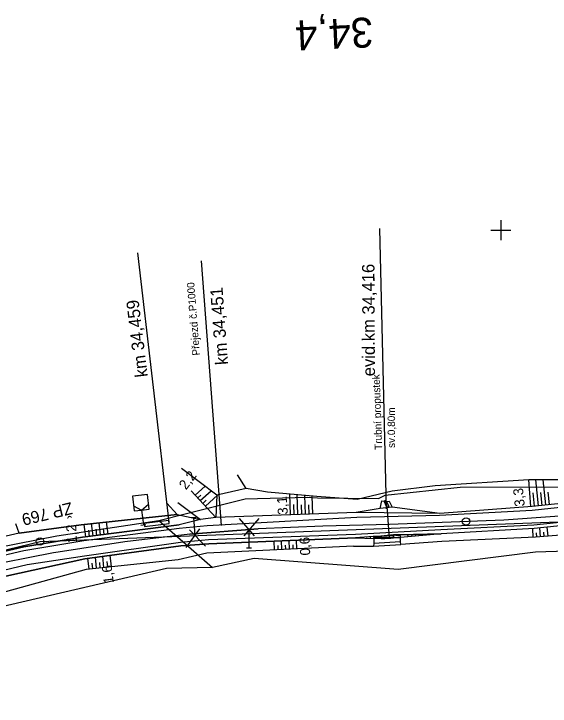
# Model space of a CAD drawing. Extents: x -805730 to -804640, y -1150889 to -1150366.
# Drawn here: x -805297.6 to -805190.1, y -1150695.5 to -1150556.6 of the extents above; entities that cross this region are included whole.
import ezdxf

# ---------------------------------------------------------------- set-up
doc = ezdxf.new("R2010")
doc.units = 0
for name, color, linetype in [('0381KM032-037P - Vrstva 1', 7, 'Continuous'), ('0381KM032-037P - Vrstva 17', 7, 'Continuous'), ('0381KM032-037P - Vrstva 19', 7, 'Continuous'), ('0381KM032-037P - Vrstva 4', 7, 'Continuous'), ('0381KM032-037P - Vrstva 48', 7, 'Continuous'), ('0381KM032-037P - Vrstva 49', 7, 'Continuous'), ('0381KM032-037P - Vrstva 51', 7, 'Continuous'), ('0381KM032-037P - Vrstva 55', 7, 'Continuous'), ('0381KM032-037P - Vrstva 7', 7, 'Continuous'), ('0381KM032-037P - Vrstva 9', 7, 'Continuous'), ('hran DP - hran DP', 7, 'Continuous'), ('krizky_1000 - Vrstva 1', 7, 'Continuous'), ('vyt_sit - ohrožené', 7, 'Continuous'), ('vyt_sit - polygon', 7, 'Continuous')]:
    doc.layers.add(name, color=color, linetype=linetype)

msp = doc.modelspace()

# ---------------------------------------------------------------- linework, layer by layer
at = {"layer": '0381KM032-037P - Vrstva 1'}
for points in [[(-805182.79, -1150656.72), (-805189.2, -1150657.4), (-805199.42, -1150658.12), (-805222.35, -1150659), (-805235.71, -1150659.34), (-805248.65, -1150659.92), (-805262.34, -1150660.99)], [(-805262.34, -1150660.99), (-805275.34, -1150662.5), (-805288.75, -1150664.54), (-805289.64, -1150664.68), (-805304.6, -1150667.62), (-805306.42, -1150668.06)]]:
    msp.add_lwpolyline(points, dxfattribs=at)
at = {"layer": '0381KM032-037P - Vrstva 17'}
for points in [[(-805070.8, -1150598.9), (-805121.06, -1150638.84), (-805152.76, -1150646.7), (-805170.92, -1150650.08), (-805194.39, -1150650.05), (-805213.2, -1150651.26), (-805221.79, -1150652.33), (-805228.79, -1150654.03)], [(-805228.79, -1150654.03), (-805236.91, -1150653.41), (-805246.77, -1150652.51), (-805251.08, -1150651.83), (-805252.77, -1150649.08)], [(-805266.94, -1150654.72), (-805264.88, -1150657), (-805284.09, -1150659.06), (-805296.52, -1150660.78), (-805297.22, -1150658.9)]]:
    msp.add_lwpolyline(points, dxfattribs=at)
at = {"layer": '0381KM032-037P - Vrstva 19'}
for p, q in [((-805224.33, -1150599.68), (-805223.01, -1150655.91)), ((-805222.9, -1150655.44), (-805223.36, -1150654.35)), ((-805222.89, -1150654.41), (-805222.49, -1150655.3)), ((-805225.47, -1150661.83), (-805224.04, -1150661.74)), ((-805224.04, -1150661.49), (-805224.04, -1150661.74)), ((-805221.51, -1150661.6), (-805224, -1150661.7)), ((-805224, -1150661.7), (-805224, -1150661.8)), ((-805224, -1150661.8), (-805221.51, -1150661.7)), ((-805223.99, -1150661.38), (-805221.54, -1150661.24)), ((-805221.51, -1150661.18), (-805221.49, -1150661.72)), ((-805221.51, -1150661.7), (-805221.51, -1150661.6))]:
    msp.add_line(p, q, dxfattribs=at)
msp.add_lwpolyline([(-805224.22, -1150655.82), (-805223.87, -1150654.3), (-805223.36, -1150654.35), (-805223.23, -1150654.21), (-805222.89, -1150654.41), (-805222.41, -1150654.36), (-805221.82, -1150655.55)], close=True, dxfattribs=at)
for points in [[(-805223.23, -1150654.21), (-805222.87, -1150655.41), (-805222.4, -1150661.78)], [(-805225.57, -1150661.42), (-805224.05, -1150661.35), (-805223.99, -1150661.38)], [(-805225.57, -1150661.42), (-805225.56, -1150661.53), (-805225.47, -1150661.83), (-805225.46, -1150662.84), (-805225.54, -1150663.4), (-805220.04, -1150663.05), (-805220.11, -1150662.52), (-805225.46, -1150662.84)], [(-805225.56, -1150661.53), (-805224.04, -1150661.49), (-805224.05, -1150661.35)], [(-805224, -1150661.7), (-805224.04, -1150661.74), (-805224.02, -1150661.84), (-805223.26, -1150661.81), (-805222.4, -1150661.78)], [(-805223.99, -1150661.81), (-805224, -1150661.8)], [(-805223.99, -1150661.38), (-805223.99, -1150661.81), (-805221.51, -1150661.69)], [(-805222.4, -1150661.78), (-805221.56, -1150661.7), (-805221.49, -1150661.72)], [(-805221.51, -1150661.7), (-805221.51, -1150661.69), (-805221.54, -1150661.24), (-805221.52, -1150661.12), (-805220.23, -1150661.07), (-805220.19, -1150661.33), (-805220.13, -1150661.62)], [(-805220.19, -1150661.33), (-805221.51, -1150661.18), (-805221.52, -1150661.12)], [(-805220.11, -1150662.52), (-805220.13, -1150661.62), (-805221.49, -1150661.72), (-805221.51, -1150661.6)]]:
    msp.add_lwpolyline(points, dxfattribs=at)
for centre, major_axis, ratio, start_param, end_param in [((-805222.69, -1150655.38), (0.215, 0.047), 0.800066, 3.235081, 6.495155), ((-805222.47, -1150661.77), (-0.4, -0.017), 0.197294, 3.17264, 6.315874), ((-805222.47, -1150661.77), (0.4, 0.019), 0.014453, 3.164337, 6.322931)]:
    msp.add_ellipse(centre, major_axis=major_axis, ratio=ratio, start_param=start_param, end_param=end_param, dxfattribs=at)
at = {"layer": '0381KM032-037P - Vrstva 4'}
for p, q in [((-805260.04, -1150606.16), (-805256.03, -1150659.22)), ((-805261.09, -1150657.61), (-805262.09, -1150657.68)), ((-805261.59, -1150657.65), (-805261.34, -1150661.14)), ((-805252.46, -1150657.82), (-805249.46, -1150661.32)), ((-805251.46, -1150661.32), (-805248.46, -1150657.82)), ((-805260.43, -1150659.92), (-805263.17, -1150663.62)), ((-805259.18, -1150663.34), (-805262.42, -1150660.06)), ((-805262.34, -1150660.99), (-805248.65, -1150659.92)), ((-805250.46, -1150663.67), (-805250.46, -1150660.17)), ((-805250.96, -1150663.67), (-805249.96, -1150663.67))]:
    msp.add_line(p, q, dxfattribs=at)
for points in [[(-805097.6, -1150634.39), (-805112.1, -1150639.75), (-805119.36, -1150642.27), (-805152.08, -1150650.89), (-805169.94, -1150653.7), (-805193.71, -1150656.24), (-805212.28, -1150657.22)], [(-805096.44, -1150637.01), (-805110.9, -1150642.46), (-805118.26, -1150644.98), (-805151.42, -1150653.61), (-805169.41, -1150656.67), (-805193.4, -1150659.17), (-805212.01, -1150660.08)], [(-805134.98, -1150644.55), (-805152.23, -1150649.93), (-805170.06, -1150652.94), (-805193.76, -1150655.4), (-805212.2, -1150656.84), (-805228.99, -1150656.61)], [(-805134.56, -1150650.98), (-805151.31, -1150654.12), (-805169.36, -1150657.36), (-805193.31, -1150659.84), (-805211.96, -1150660.88), (-805220.23, -1150661.07)], [(-805228.99, -1150656.61), (-805257.13, -1150657.62), (-805260.23, -1150658.03), (-805264.49, -1150659.11), (-805283.86, -1150661.58), (-805295.64, -1150663.5), (-805324.06, -1150670.09), (-805365.63, -1150680.4), (-805372.09, -1150681.89), (-805381.91, -1150683.24), (-805417.14, -1150687.42), (-805420, -1150686.97)], [(-805212.28, -1150657.22), (-805228.89, -1150657.63), (-805258.88, -1150659.27), (-805264.46, -1150659.8), (-805283.61, -1150662.28), (-805295.6, -1150664.3), (-805323.97, -1150670.91), (-805365.39, -1150681.52), (-805371.9, -1150683.14), (-805381.67, -1150685.01), (-805417.27, -1150688.09), (-805420, -1150686.97)], [(-805212.01, -1150660.08), (-805229.13, -1150661), (-805258.58, -1150662.1), (-805264.18, -1150662.62), (-805283.43, -1150665.36), (-805294.93, -1150667.11), (-805323.21, -1150673.86), (-805364.72, -1150684.28), (-805371.95, -1150685.67), (-805381.73, -1150687.49), (-805401.63, -1150689.36), (-805419.33, -1150691.07), (-805419.49, -1150691.68)], [(-805225.57, -1150661.42), (-805229.16, -1150661.68), (-805258.55, -1150662.93), (-805264.16, -1150663.27), (-805283.37, -1150665.88), (-805323.33, -1150674.68), (-805364.37, -1150685.33), (-805371.95, -1150687.26), (-805381.71, -1150688.97), (-805419.49, -1150691.68)]]:
    msp.add_lwpolyline(points, dxfattribs=at)
at = {"layer": '0381KM032-037P - Vrstva 48'}
for p, q in [((-805193.97, -1150655.42), (-805194.39, -1150650.05)), ((-805192.48, -1150655.27), (-805193.02, -1150650.05)), ((-805190.99, -1150655.11), (-805191.51, -1150650.05)), ((-805261.25, -1150653.12), (-805259.3, -1150651.33)), ((-805260.24, -1150654.23), (-805258.08, -1150652.25)), ((-805260.75, -1150653.68), (-805260.13, -1150653.11)), ((-805259.22, -1150655.33), (-805256.81, -1150653.11)), ((-805242.17, -1150657.08), (-805242.32, -1150652.92)), ((-805240.67, -1150657.03), (-805240.81, -1150653.06)), ((-805239.17, -1150656.98), (-805239.31, -1150653.2)), ((-805237.67, -1150656.92), (-805237.8, -1150653.33)), ((-805193.23, -1150655.34), (-805193.5, -1150652.7)), ((-805191.73, -1150655.19), (-805192, -1150652.62)), ((-805190.24, -1150655.03), (-805190.5, -1150652.54)), ((-805259.73, -1150654.78), (-805259.05, -1150654.16)), ((-805241.42, -1150657.06), (-805241.49, -1150655.02)), ((-805239.92, -1150657), (-805239.99, -1150655.06)), ((-805238.42, -1150656.95), (-805238.49, -1150655.11)), ((-805283.2, -1150661.49), (-805283.52, -1150659)), ((-805281.71, -1150661.3), (-805282.03, -1150658.84)), ((-805280.22, -1150661.11), (-805280.54, -1150658.68)), ((-805278.74, -1150660.93), (-805279.04, -1150658.52)), ((-805282.46, -1150661.4), (-805282.61, -1150660.16)), ((-805280.97, -1150661.21), (-805281.12, -1150659.98)), ((-805279.48, -1150661.02), (-805279.64, -1150659.81)), ((-805193.54, -1150661.57), (-805193.62, -1150659.86)), ((-805192.05, -1150661.47), (-805192.19, -1150659.72)), ((-805191.3, -1150661.41), (-805191.37, -1150660.53)), ((-805190.55, -1150661.35), (-805190.69, -1150659.57)), ((-805227.71, -1150661.57), (-805227.7, -1150661.74)), ((-805226.96, -1150661.52), (-805226.95, -1150661.64)), ((-805226.21, -1150661.47), (-805226.19, -1150661.8)), ((-805218.69, -1150661.03), (-805218.68, -1150661.49)), ((-805217.94, -1150661.02), (-805217.94, -1150661.22)), ((-805217.19, -1150661), (-805217.18, -1150661.35)), ((-805216.44, -1150660.98), (-805216.44, -1150661.13)), ((-805215.69, -1150660.96), (-805215.68, -1150661.22)), ((-805192.79, -1150661.53), (-805192.86, -1150660.66)), ((-805245.37, -1150664.11), (-805245.45, -1150662.37)), ((-805244.62, -1150664.07), (-805244.66, -1150663.21)), ((-805243.87, -1150664.03), (-805243.95, -1150662.31)), ((-805243.12, -1150664), (-805243.16, -1150663.14)), ((-805242.37, -1150663.96), (-805242.45, -1150662.25)), ((-805241.62, -1150663.93), (-805241.66, -1150663.07)), ((-805240.87, -1150663.89), (-805240.95, -1150662.18)), ((-805282.53, -1150667.97), (-805282.76, -1150665.8)), ((-805281.04, -1150667.81), (-805281.27, -1150665.6)), ((-805279.55, -1150667.65), (-805279.78, -1150665.39)), ((-805278.05, -1150667.5), (-805278.3, -1150665.19)), ((-805281.78, -1150667.89), (-805281.9, -1150666.79)), ((-805280.29, -1150667.73), (-805280.41, -1150666.61)), ((-805278.8, -1150667.58), (-805278.92, -1150666.44))]:
    msp.add_line(p, q, dxfattribs=at)
at = {"layer": '0381KM032-037P - Vrstva 49'}
for p, q in [((-805257.13, -1150657.62), (-805262.06, -1150652.24)), ((-805256.9, -1150653.13), (-805257.13, -1150657.62)), ((-805224.04, -1150661.74), (-805225.47, -1150661.83)), ((-805220.23, -1150661.07), (-805211.96, -1150660.88))]:
    msp.add_line(p, q, dxfattribs=at)
for points in [[(-805070.8, -1150598.9), (-805121.06, -1150638.84), (-805152.76, -1150646.7), (-805170.92, -1150650.08), (-805194.39, -1150650.05), (-805213.2, -1150651.26), (-805221.79, -1150652.33), (-805228.79, -1150654.03)], [(-805134.98, -1150644.55), (-805152.23, -1150649.93), (-805170.06, -1150652.94), (-805193.76, -1150655.4), (-805212.2, -1150656.84), (-805221.82, -1150655.55)], [(-805228.79, -1150654.03), (-805236.91, -1150653.41), (-805246.77, -1150652.51), (-805251.08, -1150651.83), (-805256.9, -1150653.13), (-805263.99, -1150647.81)], [(-805134.43, -1150652.2), (-805150.83, -1150656.03), (-805168.82, -1150659.61), (-805193.05, -1150661.55), (-805211.83, -1150662.42), (-805220.04, -1150663.05)], [(-805151.31, -1150654.12), (-805169.36, -1150657.36), (-805193.31, -1150659.84), (-805211.96, -1150660.88), (-805220.13, -1150661.62)], [(-805221.82, -1150655.55), (-805224.22, -1150655.82), (-805228.99, -1150656.61), (-805257.13, -1150657.62)], [(-805296.52, -1150660.78), (-805284.09, -1150659.06), (-805264.88, -1150657), (-805260.23, -1150658.03)], [(-805257.13, -1150657.62), (-805260.23, -1150658.03), (-805264.49, -1150659.11)], [(-805420, -1150686.97), (-805417.14, -1150687.42), (-805381.91, -1150683.24), (-805372.09, -1150681.89), (-805365.63, -1150680.4), (-805324.06, -1150670.09), (-805295.64, -1150663.5), (-805283.86, -1150661.58), (-805264.49, -1150659.11)], [(-805372.13, -1150688.5), (-805323.33, -1150674.68), (-805283.37, -1150665.88), (-805264.16, -1150663.27), (-805258.55, -1150662.93), (-805229.16, -1150661.68), (-805225.47, -1150661.83)], [(-805296.52, -1150660.78), (-805324.89, -1150667.28), (-805344.39, -1150673.21)], [(-805220.23, -1150661.07), (-805221.52, -1150661.12), (-805224.05, -1150661.35), (-805225.57, -1150661.42), (-805229.16, -1150661.68)], [(-805224.04, -1150661.74), (-805224.02, -1150661.84), (-805223.26, -1150661.81), (-805222.4, -1150661.78), (-805221.56, -1150661.7)], [(-805221.56, -1150661.7), (-805221.49, -1150661.72), (-805220.13, -1150661.62)], [(-805229.52, -1150663.36), (-805258.94, -1150664.75), (-805264.69, -1150666.1), (-805283.13, -1150668.03), (-805332.88, -1150681.81), (-805363.18, -1150690.85)], [(-805229.52, -1150663.36), (-805225.54, -1150663.4), (-805220.04, -1150663.05)]]:
    msp.add_lwpolyline(points, dxfattribs=at)
at = {"layer": '0381KM032-037P - Vrstva 51'}
msp.add_line((-805264.77, -1150654.58), (-805260.23, -1150658.03), dxfattribs=at)
msp.add_lwpolyline([(-805262.06, -1150652.24), (-805257.13, -1150657.62), (-805260.23, -1150658.03)], dxfattribs=at)
at = {"layer": '0381KM032-037P - Vrstva 55'}
msp.add_line((-805268.53, -1150658.22), (-805257.77, -1150667.64), dxfattribs=at)
at = {"layer": '0381KM032-037P - Vrstva 7'}
for p, q in [((-805272, -1150656.13), (-805271.65, -1150659.11)), ((-805272.15, -1150659.17), (-805271.16, -1150659.05))]:
    msp.add_line(p, q, dxfattribs=at)
for points in [[(-805272, -1150656.13), (-805270.51, -1150655.96), (-805270.85, -1150652.98), (-805273.83, -1150653.32), (-805273.49, -1150656.3), (-805272, -1150656.13)], [(-805273.6, -1150655.31), (-805272, -1150656.13), (-805270.62, -1150654.96)]]:
    msp.add_lwpolyline(points, dxfattribs=at)
msp.add_circle((-805206.98, -1150658.41), 0.75, dxfattribs=at)
at = {"layer": '0381KM032-037P - Vrstva 9'}
for p, q in [((-805266.48, -1150658.55), (-805272.73, -1150604.53)), ((-805266.52, -1150658.25), (-805266.59, -1150657.67)), ((-805266.52, -1150658.25), (-805271.48, -1150658.85)), ((-805271.48, -1150658.85), (-805271.41, -1150659.44)), ((-805271.41, -1150659.44), (-805266.45, -1150658.84)), ((-805266.45, -1150658.84), (-805266.52, -1150658.25))]:
    msp.add_line(p, q, dxfattribs=at)
at = {"layer": 'hran DP - hran DP'}
for p, q in [((-805223.22, -1150653.17), (-805208.17, -1150651.53)), ((-805208.17, -1150651.53), (-805178.93, -1150651.45)), ((-805251.25, -1150653.89), (-805238.75, -1150653.54)), ((-805238.75, -1150653.54), (-805236.73, -1150653.66)), ((-805236.73, -1150653.66), (-805224.51, -1150653.79)), ((-805224.51, -1150653.79), (-805223.22, -1150653.17)), ((-805259.03, -1150655.84), (-805251.25, -1150653.89)), ((-805263.04, -1150656.84), (-805259.03, -1150655.84)), ((-805268.53, -1150658.22), (-805263.04, -1150656.84)), ((-805288.99, -1150661.29), (-805268.53, -1150658.22)), ((-805313.93, -1150666.21), (-805288.99, -1150661.29)), ((-805193.03, -1150664.54), (-805220.59, -1150668.04)), ((-805161.69, -1150663.73), (-805193.03, -1150664.54)), ((-805249.45, -1150665.86), (-805257.77, -1150667.64)), ((-805220.59, -1150668.04), (-805249.45, -1150665.86)), ((-805267.02, -1150667.87), (-805308.19, -1150677.39)), ((-805257.77, -1150667.64), (-805267.02, -1150667.87))]:
    msp.add_line(p, q, dxfattribs=at)
at = {"layer": 'krizky_1000 - Vrstva 1'}
for points in [[(-805200, -1150598), (-805200, -1150602)], [(-805202, -1150600), (-805198, -1150600)]]:
    msp.add_lwpolyline(points, dxfattribs=at)
at = {"layer": 'vyt_sit - ohrožené'}
msp.add_line((-805292.41, -1150662.43), (-805292.31, -1150662.43), dxfattribs=at)
msp.add_circle((-805292.36, -1150662.43), 0.756, dxfattribs=at)
at = {"layer": 'vyt_sit - polygon'}
for p, q in [((-805292.36, -1150662.43), (-805154.33, -1150657.15)), ((-805426.99, -1150695.45), (-805292.36, -1150662.43))]:
    msp.add_line(p, q, dxfattribs=at)

# ---------------------------------------------------------------- texts
at = {"layer": '0381KM032-037P - Vrstva 19'}
for s, height, rotation, p in [('evid.km 34,416', 2.4868, 90.2833, (-805225.23, -1150629.29)), ('Trubní propustek', 1.4998, 91.9626, (-805223.77, -1150644.03)), ('sv.0,80m', 1.5, 89.9669, (-805221.21, -1150643.67))]:
    msp.add_text(s, height=height, rotation=rotation, dxfattribs=at).set_placement(p)
at = {"layer": '0381KM032-037P - Vrstva 4'}
for s, height, rotation, p in [('Přejezd č.P1000', 1.5, 94.4666, (-805260.31, -1150625.07)), ('km 34,451', 2.5, 94.1036, (-805254.68, -1150626.93))]:
    msp.add_text(s, height=height, rotation=rotation, dxfattribs=at).set_placement(p)
at = {"layer": '0381KM032-037P - Vrstva 48'}
for s, rotation, p in [('2,2', 53.0616, (-805263.1, -1150652.2)), ('3,3', 95.9333, (-805195.2, -1150655.32)), ('3,1', 94.1143, (-805242.68, -1150657)), ('1,2', 93.2392, (-805284.93, -1150662.67)), ('0,6', 92.4516, (-805238.21, -1150665.19)), ('1,6', 97.414, (-805277.56, -1150670.74))]:
    msp.add_text(s, height=2, rotation=rotation, dxfattribs=at).set_placement(p)
at = {"layer": '0381KM032-037P - Vrstva 7'}
msp.add_text('34,4', height=6, rotation=182.5512, dxfattribs=at).set_placement((-805225.74, -1150557.29))
at = {"layer": '0381KM032-037P - Vrstva 9'}
msp.add_text('km 34,459', height=2.5, rotation=96.8511, dxfattribs=at).set_placement((-805270.76, -1150629.34))
at = {"layer": 'vyt_sit - ohrožené'}
msp.add_text('ŽP 769', height=2.4, rotation=193.6062, dxfattribs=at).set_placement((-805286.16, -1150654.52))

doc.saveas('drawing.dxf')
